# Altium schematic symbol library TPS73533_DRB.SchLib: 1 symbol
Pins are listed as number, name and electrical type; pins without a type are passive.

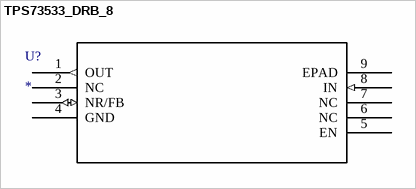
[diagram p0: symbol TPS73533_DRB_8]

## TPS73533_DRB_8
designator U?
Imported; Manufacturer_Part_Number: tps73533_drb_8; GENERIC_PART_NUMBER: TPS73533; Vendor: Texas Instruments; PACKAGE_DESIGNATOR: DRB; PIN_COUNT: 8; FAMILY_NAME: SINGLE CHANNEL LDO; INDUSTRY_STD_PKG_TYPE: SON
footprint DRB8_1P75X1P5
pins: 1 OUT (out), 2 NC, 3 NR/FB (io), 4 GND (power), 5 EN, 6 NC, 7 NC, 8 IN (in), 9 EPAD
